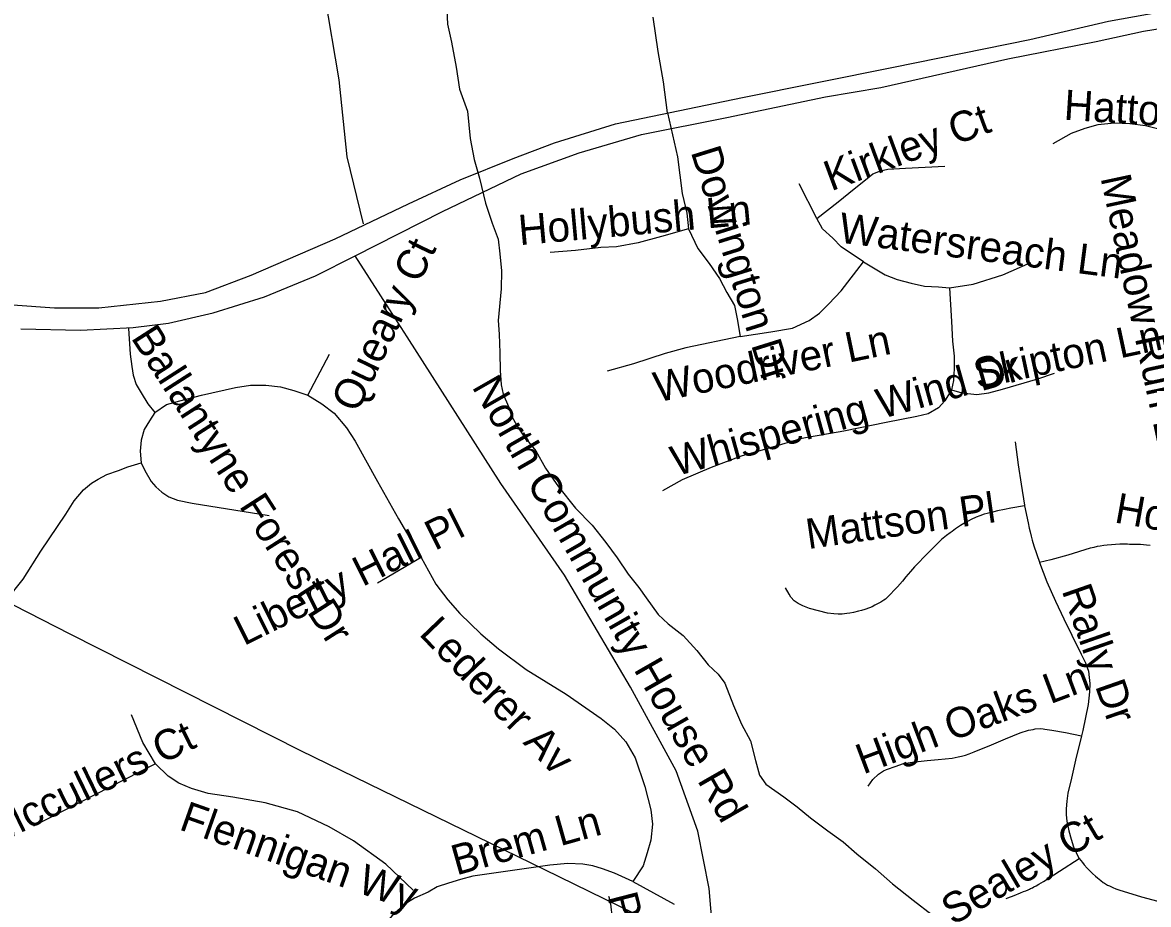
# Model space of a CAD drawing. Extents: x 1383679 to 1536984, y 460658 to 651027.
# Drawn here: x 1449678 to 1453218, y 477874 to 480647 of the extents above; entities that cross this region are included whole.
import ezdxf

# ---------------------------------------------------------------- set-up
doc = ezdxf.new("R2010")
doc.units = 0
for name, color, linetype in [('Exist Hydrographic Misc Water Feature', 7, 'Continuous'), ('Exist Road Non-System Type 51', 7, 'Continuous'), ('Exist Road Non-System Type 51 Label', 7, 'Continuous'), ('Exist Utilities Electrical Transmission Line', 7, 'Continuous')]:
    doc.layers.add(name, color=color, linetype=linetype)

msp = doc.modelspace()

# ---------------------------------------------------------------- linework, layer by layer
at = {"layer": 'Exist Hydrographic Misc Water Feature'}
msp.add_lwpolyline([(1451011, 480708.3), (1451013.9, 480641.8), (1451026.8, 480585.7), (1451041.4, 480507.5), (1451052.1, 480437.5), (1451076.9, 480368.9), (1451085.3, 480282.6), (1451098.1, 480216.7), (1451115, 480158.1), (1451133.7, 480079.7), (1451154.5, 480016.9), (1451173.6, 479966.5), (1451178.7, 479920.5), (1451183.7, 479867), (1451182.7, 479810.4), (1451172.9, 479710.5), (1451176.1, 479667), (1451179, 479608.6), (1451180, 479552.8), (1451183.3, 479508.4), (1451188.8, 479478.8), (1451206, 479439.9), (1451215.4, 479410.1), (1451232.8, 479377.8), (1451254.3, 479347), (1451291.5, 479300.3), (1451322.6, 479245.5), (1451363.5, 479187.2), (1451416.3, 479120.5), (1451469.3, 479066.9), (1451512.3, 479011.9), (1451547.4, 478963.6), (1451582.5, 478912.8), (1451615.8, 478870.3), (1451639.2, 478837.8), (1451676.3, 478785.4), (1451707.6, 478756.8), (1451755, 478719.8), (1451798.2, 478673), (1451833.4, 478628), (1451864.9, 478597.8), (1451886.3, 478569.5), (1451913.2, 478499.1), (1451938, 478440.4), (1451967.1, 478388.1), (1451982, 478327.1), (1451995.1, 478280.9), (1452014.7, 478252.6), (1452071.9, 478212), (1452113.3, 478180.8), (1452154.9, 478146.3), (1452210.1, 478105), (1452257.5, 478070.4), (1452300.8, 478033.5), (1452359.9, 477986.3), (1452413.1, 477939.3), (1452478.1, 477887.9), (1452537.4, 477840.8)], dxfattribs=at)
at = {"layer": 'Exist Road Non-System Type 51'}
msp.add_line((1450096, 478315.9), (1449713, 478120.4), dxfattribs=at)
for points in [[(1450749.7, 480014.5), (1450698.7, 480224.9), (1450673.3, 480467.1), (1450628.7, 480734.9), (1450590.4, 480919.8), (1450501.3, 481155.6), (1450367.5, 481410.6), (1450233.7, 481665.6), (1450138.1, 481869.6), (1450042.6, 482086.4), (1449978.9, 482328.6), (1449953.4, 482577.3), (1449953.4, 482832.3), (1449985.2, 483189.3)], [(1449647.2, 479759.6), (1449778.8, 479750), (1449918.5, 479750), (1450112, 479771.3), (1450253.6, 479798.4), (1450397.2, 479852.5), (1450660.5, 479966.7), (1450891.9, 480077), (1451053.5, 480152.5), (1451221, 480220.3), (1451350.7, 480268.6), (1451542.2, 480328.6), (1451941.1, 480411.9), (1452415.9, 480506.7), (1452844.8, 480593.8), (1453092.1, 480651.8), (1453255.7, 480680.9)], [(1451706.2, 480363.2), (1451693.7, 480460.9), (1451676.1, 480556.1), (1451661.1, 480663.8)], [(1450723.9, 479913.9), (1450998.8, 480052.9), (1451246, 480171.6), (1451428.1, 480237.5), (1451623.7, 480295.5), (1451892.7, 480348.2), (1452202.5, 480414.1), (1452376.4, 480443.1), (1452775.9, 480532.8), (1453053, 480588.1), (1453202.5, 480619.8), (1453365.5, 480646.1)], [(1451706.2, 480363.2), (1451736.9, 480224.9), (1451751.6, 480110.1), (1451766.3, 480048.3), (1451772.2, 479998.3)], [(1453350.3, 480257.4), (1453314.9, 480287.4), (1453271.4, 480306.5), (1453208.7, 480322.8), (1453159.7, 480328.3), (1453110.7, 480331), (1453059, 480325.5), (1453018.1, 480314.6), (1452974.6, 480298.3), (1452917.4, 480265.6)], [(1452175.1, 480030.7), (1452242.7, 480083.6), (1452292.7, 480124.8), (1452333.9, 480157.2), (1452351.5, 480171.9), (1452375, 480180.8), (1452398.6, 480186.6), (1452454.4, 480189.6), (1452577.9, 480195.5)], [(1452175.1, 480030.7), (1452119.2, 480139.6)], [(1452322.1, 479895.3), (1452251.5, 479942.4), (1452225.1, 479968.9), (1452192.7, 479998.3), (1452175.1, 480030.7)], [(1451772.2, 479998.3), (1451686.9, 479974.8), (1451613.4, 479954.2), (1451545.8, 479942.4), (1451495.8, 479939.4), (1451416.4, 479930.6), (1451337, 479924.7)], [(1451772.2, 479998.3), (1451801.6, 479936.5), (1451836.9, 479889.4), (1451869.2, 479842.3), (1451892.8, 479798.2), (1451916.3, 479757), (1451925.1, 479715.8), (1451933.9, 479659.9)], [(1449672.7, 479683.9), (1449860.6, 479680.3), (1450026.2, 479688), (1450137.4, 479702.3), (1450277.5, 479734.5), (1450439.1, 479784.8), (1450598.7, 479850.6), (1450723.9, 479913.9)], [(1451846.1, 477102.5), (1451840.4, 477378.7), (1451852.4, 477738.7), (1451836.5, 477924.5), (1451800.6, 478104.5), (1451732.7, 478294.2), (1451589.1, 478557.5), (1451381.7, 478909.7), (1451182.2, 479198.1), (1450887, 479658.8), (1450849.1, 479718), (1450723.9, 479913.9)], [(1451933.9, 479659.9), (1452031, 479674.6), (1452098.6, 479686.4), (1452151.5, 479709.9), (1452183.9, 479733.4), (1452213.3, 479762.9), (1452251.5, 479804.1), (1452322.1, 479895.3)], [(1452322.1, 479895.3), (1452389.7, 479854.1), (1452428, 479839.4), (1452472.1, 479827.6), (1452513.3, 479818.8), (1452557.4, 479815.8), (1452592.7, 479812.9)], [(1452592.7, 479812.9), (1452666.2, 479824.7), (1452760.3, 479854.1), (1452848.5, 479892.4)], [(1452592.7, 479812.9), (1452598.5, 479707), (1452601.5, 479645.2), (1452607.4, 479598.1), (1452607.4, 479559.8), (1452604.4, 479521.6), (1452598.5, 479492.1)], [(1450011.5, 479685), (1450016.4, 479604.5), (1450021.3, 479565.4), (1450026.2, 479538.6), (1450035.9, 479509.3), (1450050.6, 479482.4), (1450072.5, 479448.3), (1450094.5, 479421.4)], [(1451933.9, 479659.9), (1451763.4, 479624.6), (1451698.7, 479606.9), (1451598.7, 479574.5), (1451516.3, 479551)], [(1450574.9, 479475.1), (1450643.2, 479604.5)], [(1452598.5, 479492.1), (1452630.7, 479483.2), (1452677.9, 479477.4), (1452716.2, 479483.3), (1452758.9, 479494.4), (1452869.6, 479527), (1452922.8, 479544.5)], [(1450094.5, 479421.4), (1450131, 479445.8), (1450172.5, 479458), (1450240.8, 479475.1), (1450348.1, 479499.5), (1450394.4, 479506.8), (1450443.2, 479506.8), (1450489.5, 479502), (1450531, 479489.7), (1450574.9, 479475.1)], [(1452598.5, 479492.1), (1452577.6, 479457.5), (1452558.2, 479436.2), (1452525, 479416.8), (1452490, 479408.1), (1452392.7, 479389.1), (1452260.4, 479362.6), (1452128, 479339.1), (1452028, 479309.7), (1451936.9, 479283.2), (1451842.8, 479247.9), (1451751.6, 479209.6), (1451689.8, 479174.3)], [(1450574.9, 479475.1), (1450618.8, 479448.3), (1450657.8, 479419), (1450696.8, 479372.6), (1450723.7, 479331.1), (1450794.4, 479204.2), (1450860.2, 479087.1), (1450931, 478965)], [(1450094.5, 479421.4), (1450077.4, 479394.6), (1450060.3, 479367.7), (1450050.6, 479333.6), (1450048.1, 479299.4), (1450050.6, 479262.8)], [(1452799.1, 479328.6), (1452807.9, 479256.7), (1452817.3, 479195.3), (1452828, 479129.6), (1452828.4, 479127.4)], [(1449318.9, 478745.4), (1449377.4, 478733.2), (1449416.5, 478735.6), (1449462.8, 478738.1), (1449506.7, 478752.7), (1449540.8, 478767.3), (1449579.9, 478801.5), (1449650.6, 478860.1), (1449679.9, 478896.7), (1449736, 478984.5), (1449814, 479101.7), (1449840.8, 479143.2), (1449870.1, 479177.4), (1449894.5, 479199.3), (1449916.4, 479211.5), (1449943.3, 479226.2), (1449979.8, 479238.4), (1450009.1, 479250.6), (1450050.6, 479262.8)], [(1450050.6, 479262.8), (1450062.8, 479238.4), (1450082.3, 479204.2), (1450096.9, 479187.1), (1450116.4, 479170), (1450138.4, 479155.4), (1450165.2, 479145.6), (1450211.5, 479135.9), (1450453, 479096.8)], [(1452828.4, 479127.4), (1452784.6, 479119.8), (1452765.5, 479116), (1452743.3, 479111.4), (1452724.1, 479106.8), (1452710.2, 479103.5), (1452701.6, 479100.8), (1452687.8, 479096.3), (1452676.3, 479091.6), (1452660.7, 479084.8), (1452650.9, 479079.7), (1452642.7, 479075.3), (1452637.3, 479072.2), (1452627.3, 479065.9), (1452611.3, 479055.2), (1452600.5, 479047.1), (1452594.4, 479042.9), (1452583.3, 479034.5), (1452577.6, 479029.9), (1452567.6, 479021.9), (1452547.4, 479002), (1452525.2, 478979.4), (1452481.9, 478935.8), (1452469.7, 478920.9), (1452455.5, 478904.1), (1452444.4, 478891.1), (1452428.4, 478873.1), (1452418.8, 478862.4), (1452407.3, 478849.8), (1452398.1, 478841), (1452390.9, 478834.5), (1452385.9, 478831), (1452376.7, 478824.9), (1452368.3, 478819.9), (1452358, 478815), (1452349.2, 478810.4), (1452340.4, 478806.6), (1452325.8, 478801.2), (1452315.9, 478798.5), (1452306.7, 478795.8), (1452290.2, 478791.6), (1452278.8, 478789.7), (1452269.2, 478788.6), (1452254.7, 478786.7), (1452242, 478787), (1452229, 478787.8), (1452208.7, 478790.1), (1452180, 478797), (1452152.5, 478804.6), (1452131.1, 478813.1), (1452116.9, 478820.3), (1452103.5, 478829.1), (1452093.9, 478840.2), (1452087.8, 478849.8), (1452076.3, 478869.3)], [(1452828.4, 479127.4), (1452839.3, 479073.8), (1452843, 479057.1), (1452845.7, 479046), (1452849.1, 479032.4), (1452852.4, 479019.2), (1452857.5, 479002), (1452875.2, 478950.4), (1452875.6, 478949.1)], [(1453222.8, 479003.2), (1453211.7, 479004.3), (1453192.6, 479006), (1453172.1, 479006.3), (1453158.5, 479006.4), (1453152.3, 479006.7), (1453127.7, 479006.7), (1453087.7, 479004.3), (1453077.9, 479003.1), (1453066.4, 479001.1), (1453056.9, 478999.5), (1453046, 478997), (1453041.2, 478995.7), (1453034, 478994), (1452963.9, 478972.7), (1452911.2, 478957.5), (1452875.6, 478949.1)], [(1450931, 478965), (1450794.4, 478884.5)], [(1450931, 478965), (1450977, 478881.5), (1451015, 478831.6), (1451052.9, 478788.9), (1451119.4, 478724.8), (1451174, 478677.3), (1451261.8, 478613.1), (1451387.6, 478534.8), (1451496.8, 478458.8), (1451539.5, 478425.5), (1451575.1, 478385.1), (1451603.6, 478335.3), (1451634.4, 478245), (1451653.4, 478171.4), (1451658.2, 478126.3), (1451653.4, 478076.4), (1451641.5, 478036), (1451629.7, 477995.6), (1451596.4, 477945.7)], [(1452875.6, 478949.1), (1452898.7, 478888.1), (1452925.3, 478827.9), (1452952.1, 478772.4), (1452977, 478720.6), (1453005.7, 478661.1), (1453019.9, 478633.4), (1453029.2, 478607.1), (1453031.7, 478587.5), (1453033.3, 478568.6), (1453032.1, 478542.6), (1453027.7, 478502.7), (1453011.5, 478421.3), (1453007.2, 478404.3)], [(1450096, 478315.9), (1450056.1, 478383.6), (1450020.2, 478470.7)], [(1452337.1, 478246.1), (1452351.1, 478267.2), (1452368.7, 478284.1), (1452384.7, 478294), (1452393.9, 478298.2), (1452424.2, 478309.3), (1452444.8, 478315.8), (1452455.1, 478318.5), (1452475.8, 478321.5), (1452484.6, 478322.7), (1452522.1, 478326.5), (1452556.2, 478329.6), (1452578.4, 478331.9), (1452600.2, 478334.5), (1452619.3, 478338), (1452630, 478340.7), (1452642.6, 478343.7), (1452654.1, 478347.6), (1452669.5, 478353.4), (1452724, 478376.3), (1452768.2, 478394.4), (1452814.7, 478413.5), (1452840.7, 478421.7), (1452855, 478424.4), (1452862.1, 478425.8), (1452878.3, 478427.1), (1452886.5, 478426.4), (1452891.7, 478425.6), (1452914.1, 478422.5), (1452957, 478415), (1453007.2, 478404.3)], [(1453007.2, 478404.3), (1452987.9, 478328), (1452975.5, 478271.6), (1452964.3, 478223.5), (1452960.7, 478198.3), (1452959.2, 478174.2), (1452959.4, 478155.7), (1452961.3, 478135.8), (1452967.7, 478105), (1452974.7, 478078.9), (1452982.6, 478055.4), (1452987.2, 478044.4), (1452990.7, 478037.1), (1452995.2, 478027.8), (1453000.4, 478019)], [(1450905.9, 477919.1), (1450820.1, 478000.4), (1450718.4, 478073.9), (1450642.6, 478118.5), (1450542.8, 478164.9), (1450441.1, 478193.9), (1450339.4, 478211.4), (1450261.6, 478223), (1450209.7, 478238.4), (1450169.8, 478255.9), (1450135.9, 478277.2), (1450096, 478315.9)], [(1452770.7, 477892.4), (1452776, 477894.4), (1452796.1, 477902.4), (1452815.9, 477910.4), (1452825.2, 477914.2), (1452832.1, 477917), (1452839.6, 477920.2), (1452843.4, 477922.2), (1452847.3, 477923.9), (1452852.8, 477926.6), (1452857.3, 477929.1), (1452864.6, 477933), (1452872.8, 477937.5), (1452880.8, 477942.1), (1452888.1, 477946.4), (1452937.7, 477978.7), (1453000.4, 478019)], [(1453000.4, 478019), (1453004.7, 478012.7), (1453010.3, 478005.6), (1453015.9, 477998.7), (1453024.7, 477988.2), (1453030.5, 477982.4), (1453042.2, 477971.6), (1453051.1, 477963.3), (1453057.6, 477957.9), (1453068.2, 477949.2), (1453075.9, 477943.4), (1453079.7, 477940.7), (1453085.9, 477936.9), (1453089.5, 477935), (1453095.1, 477932.1), (1453105.9, 477927.1), (1453115.1, 477923.6), (1453127.3, 477919.2), (1453138.5, 477915.7), (1453196, 477897.7), (1453231.6, 477888.1), (1453286.5, 477874.2)], [(1451596.4, 477945.7), (1451539.5, 477971.9), (1451501.5, 477986.1), (1451470.7, 477995.6), (1451439.8, 478000.4), (1451392.3, 478002.7), (1451335.4, 477998), (1451093.3, 477962.4), (1451055.3, 477952.9), (1451017.3, 477941), (1450981.7, 477929.1), (1450953.3, 477912.5), (1450910.5, 477893.5), (1450879.7, 477874.5)], [(1451596.4, 477945.7), (1451727, 477874.5)], [(1451846.1, 477102.5), (1451803.9, 477110), (1451780.3, 477115.7), (1451735.2, 477203.3), (1451702.9, 477264.2), (1451670.4, 477342.9), (1451640.2, 477413.6), (1451622.9, 477453.6), (1451601.9, 477516.3), (1451581.7, 477579.5), (1451562, 477643.8), (1451548.7, 477693.1), (1451540.6, 477741.9), (1451537.6, 477786.3), (1451532.4, 477829.8), (1451527.4, 477876.1), (1451525.9, 477883.7), (1451523, 477893.4), (1451521.4, 477899.3)], [(1450681.6, 477537.2), (1450752.3, 477727.5), (1450796.1, 477788.7), (1450828, 477823.8), (1450850.2, 477849.3), (1450879.7, 477874.5)]]:
    msp.add_lwpolyline(points, dxfattribs=at)
at = {"layer": 'Exist Utilities Electrical Transmission Line'}
msp.add_lwpolyline([(1446198.1, 480546), (1446620.6, 480338.2), (1447264.8, 480008.3), (1448073.7, 479607.4), (1448375.2, 479453.9), (1449031.6, 479131.8), (1449826.6, 478725), (1450552.1, 478357.6), (1451319.5, 477983.4), (1451880.8, 477709.2), (1452378.4, 477457.9), (1453014.9, 477138.1), (1453821.9, 476745.3)], dxfattribs=at)

# ---------------------------------------------------------------- texts
at = {"layer": 'Exist Road Non-System Type 51 Label'}
for s, rotation, p in [('Hatton Ct', 356.3558, (1452950, 480341.8)), ('Kirkley Ct', 20.387, (1452219.9, 480116.2)), ('Dowington Dr', 287.3576, (1451778.2, 480241.2)), ('Meadow Run Ln', 282.0788, (1453066.8, 480159.5)), ('Hollybush Ln', 5.1251, (1451241.1, 479947)), ('Watersreach Ln', 352.6747, (1452241.1, 479956.1)), ('Queary Ct', 64.374, (1450730.5, 479416.2)), ('Ballantyne Forest Dr', 302.7205, (1450017.3, 479656.1)), ('Woodriver Ln', 11.7302, (1451673.9, 479452.6)), ('Skipton Ln', 12.0643, (1452679.5, 479495.1)), ('Whispering Wind Dr', 15.5813, (1451732.4, 479220.1)), ('North Community House Rd', 299.7927, (1451089.2, 479502.2)), ('Mattson Pl', 8.1924, (1452147.8, 478991.3)), ('Houston Ridge Rd', 349.8608, (1453107.8, 479075.8)), ('Liberty Hall Pl', 26.5028, (1450374.1, 478685.9)), ('Rally Dr', 289.2756, (1452944.2, 478861.3)), ('Lederer Av', 313.7967, (1450921.7, 478723.3)), ('High Oaks Ln', 20.5986, (1452320.7, 478282.2)), ('Mccullers Ct', 25.9583, (1449601.9, 478064.3)), ('Flennigan Wy', 340.5471, (1450166.9, 478110.7)), ('Brem Ln', 15.7527, (1451042.3, 477964.8)), ('Sealey Ct', 30.4821, (1452603.2, 477806.4)), ('Paulston Rd', 284.4837, (1451516, 477899))]:
    msp.add_text(s, height=95, rotation=rotation, dxfattribs=at).set_placement(p)

doc.saveas('drawing.dxf')
